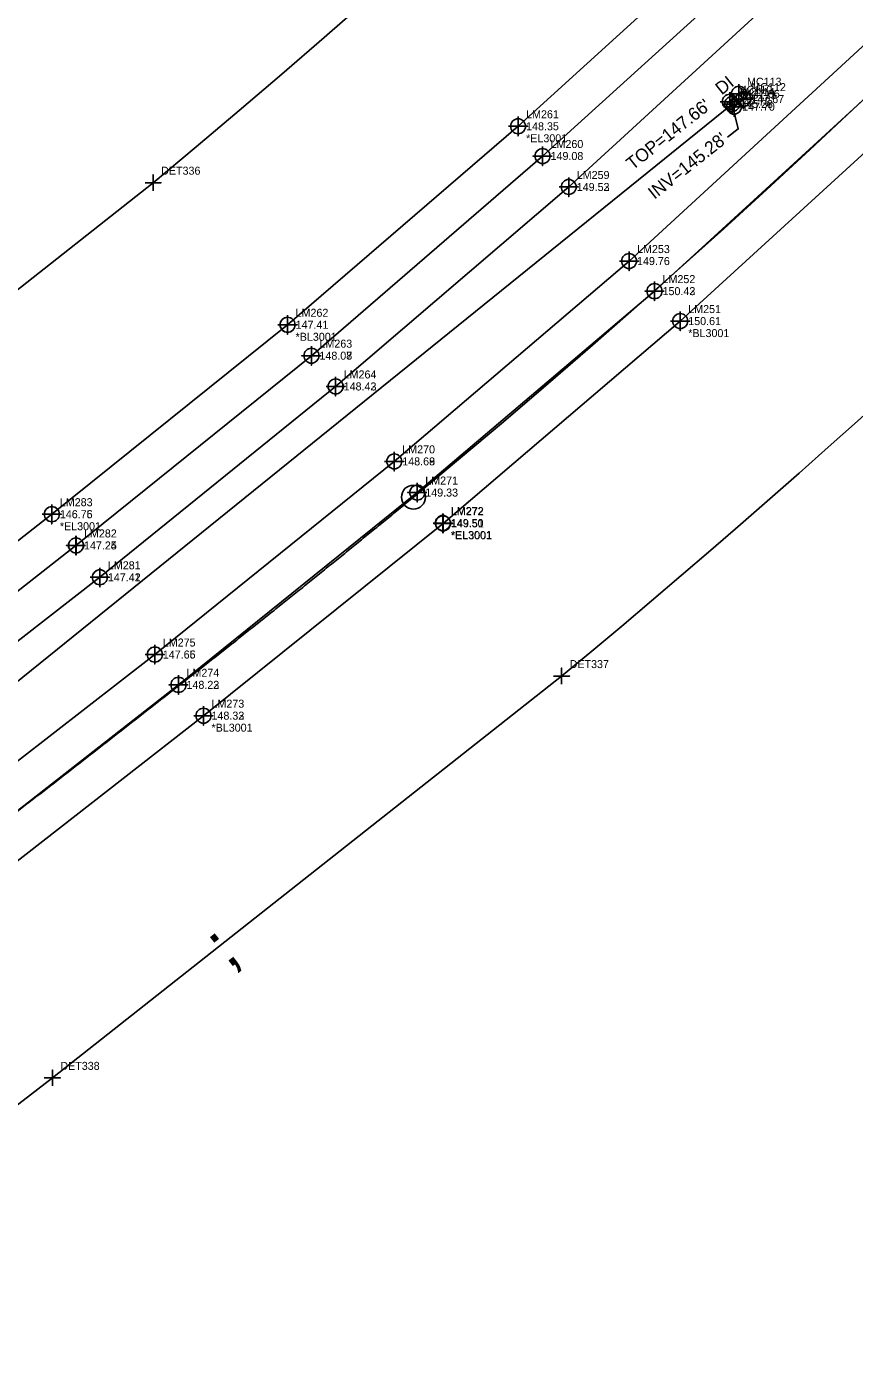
# Model space of a CAD drawing. Extents: x 2262665 to 2270527, y 505476 to 514960.
# Drawn here: x 2265152.7 to 2265411.2, y 507873.1 to 508285.7 of the extents above; entities that cross this region are included whole.
import ezdxf

# ---------------------------------------------------------------- set-up
doc = ezdxf.new("R2010")
doc.units = 0
for name, color, linetype in [('Exist Horizontal Alignment', 7, 'Continuous'), ('Exist Property Corner CELL', 7, 'Continuous'), ('Exist Property Corner Cogo Number', 7, 'Continuous'), ('Exist Right of Way Control of Access CA Symbol CELL', 7, 'Continuous'), ('Exist Right of Way Control of Access Line', 7, 'Continuous'), ('Exist Roads EOP', 7, 'Continuous'), ('Exist Roads EOP Cogo Comment', 7, 'Continuous'), ('Exist Roads EOP Cogo Elevation', 7, 'Continuous'), ('Exist Roads EOP Cogo Number', 7, 'Continuous'), ('Exist Roads EOP Cogo Point CELL', 7, 'Continuous'), ('Exist Roads EOT', 7, 'Continuous'), ('Exist Roads EOT Cogo Elevation', 7, 'Continuous'), ('Exist Roads EOT Cogo Number', 7, 'Continuous'), ('Exist Roads EOT Cogo Point CELL', 7, 'Continuous'), ('Exist Structure Minor Drop Inlet', 7, 'Continuous'), ('Exist Structure Minor Drop Inlet Cogo Elevation', 7, 'Continuous'), ('Exist Structure Minor Drop Inlet Cogo Number', 7, 'Continuous'), ('Exist Structure Minor Drop Inlet Cogo Point CELL', 7, 'Continuous'), ('Exist Structure Minor Drop Inlet Text', 7, 'Continuous'), ('Exist Structure Minor Drop Inlet Top Elevation', 7, 'Continuous'), ('Exist Structure Minor Pipes RCP 15 Inch', 7, 'Continuous'), ('Exist Structure Minor Pipes RCP 15 Inch Cogo Elevation', 7, 'Continuous'), ('Exist Structure Minor Pipes RCP 15 Inch Cogo Number', 7, 'Continuous'), ('Exist Structure Minor Pipes RCP 15 Inch Cogo Point CELL', 7, 'Continuous'), ('Exist Structure Minor Pipes RCP 15 Inch Invert', 7, 'Continuous'), ('Exist Structure Minor Pipes RCP 15 Inch Leader', 7, 'Continuous')]:
    doc.layers.add(name, color=color, linetype=linetype)

msp = doc.modelspace()

# ---------------------------------------------------------------- linework, layer by layer
at = {"layer": 'Exist Horizontal Alignment'}
msp.add_circle((2265273.5, 508138.73), 3.75, dxfattribs=at)
msp.add_arc((2263436.25, 510359.19), 2882, 309.60499, 355.6461, dxfattribs=at)
msp.add_spline([(2265116.51, 508014.84), (2265118.65, 508016.49), (2265120.79, 508018.14), (2265122.93, 508019.79), (2265125.07, 508021.44), (2265127.21, 508023.09), (2265129.35, 508024.74), (2265131.49, 508026.39), (2265133.63, 508028.04), (2265135.77, 508029.69), (2265137.91, 508031.34), (2265140.05, 508032.99), (2265142.19, 508034.64), (2265144.33, 508036.29), (2265146.47, 508037.94), (2265148.61, 508039.6), (2265150.74, 508041.25), (2265152.88, 508042.9), (2265155.02, 508044.56), (2265157.16, 508046.21), (2265159.29, 508047.87), (2265161.43, 508049.52), (2265163.57, 508051.18), (2265165.7, 508052.83), (2265167.84, 508054.49), (2265169.97, 508056.15), (2265172.11, 508057.81), (2265174.24, 508059.47), (2265176.37, 508061.13), (2265178.5, 508062.79), (2265180.64, 508064.45), (2265182.77, 508066.11), (2265184.9, 508067.77), (2265187.03, 508069.44), (2265189.16, 508071.1), (2265191.28, 508072.77), (2265193.41, 508074.44), (2265195.54, 508076.1), (2265197.67, 508077.77), (2265199.79, 508079.44), (2265201.92, 508081.11), (2265204.04, 508082.78), (2265206.16, 508084.46), (2265208.28, 508086.13), (2265210.4, 508087.81), (2265212.52, 508089.48), (2265214.64, 508091.16), (2265216.76, 508092.84), (2265218.88, 508094.52), (2265220.99, 508096.2), (2265223.11, 508097.88), (2265225.22, 508099.57), (2265227.34, 508101.25), (2265229.45, 508102.94), (2265231.56, 508104.63), (2265233.67, 508106.32), (2265235.78, 508108.01), (2265237.88, 508109.7), (2265239.99, 508111.4), (2265242.09, 508113.09), (2265244.2, 508114.79), (2265246.3, 508116.49), (2265248.4, 508118.19), (2265250.5, 508119.89), (2265252.6, 508121.59), (2265254.69, 508123.3), (2265256.79, 508125.01), (2265258.88, 508126.72), (2265260.97, 508128.43), (2265263.07, 508130.14), (2265265.15, 508131.85), (2265267.24, 508133.57), (2265269.33, 508135.29), (2265271.41, 508137.01), (2265273.5, 508138.73)], degree=3, dxfattribs=at)
at = {"layer": 'Exist Property Corner CELL'}
for p, q in [((2265192.25, 508236.92), (2265192.25, 508236.92)), ((2265319.75, 508082.83), (2265319.75, 508082.83)), ((2265160.79, 507957.36), (2265160.79, 507957.36))]:
    msp.add_line(p, q, dxfattribs=at)
for points in [[(2265189.75, 508236.92), (2265194.75, 508236.92), (2265192.25, 508236.92), (2265192.25, 508239.42), (2265192.25, 508234.42)], [(2265317.25, 508082.83), (2265322.25, 508082.83), (2265319.75, 508082.83), (2265319.75, 508085.33), (2265319.75, 508080.33)], [(2265158.29, 507957.36), (2265163.29, 507957.36), (2265160.79, 507957.36), (2265160.79, 507959.86), (2265160.79, 507954.86)]]:
    msp.add_lwpolyline(points, dxfattribs=at)
at = {"layer": 'Exist Right of Way Control of Access CA Symbol CELL'}
msp.add_line((2265216.9, 508001.65), (2265216.9, 508001.65), dxfattribs=at)
at = {"layer": 'Exist Right of Way Control of Access Line'}
for p, q in [((2265038.72, 508115.78), (2265192.25, 508236.92)), ((2265160.79, 507957.36), (2265319.75, 508082.83)), ((2264610.44, 507533.27), (2265160.79, 507957.36))]:
    msp.add_line(p, q, dxfattribs=at)
for radius, end in [(2754.56, 355.6461), (2954.56, 339.73535)]:
    msp.add_arc((2263436.25, 510359.19), radius, 309.60499, end, dxfattribs=at)
at = {"layer": 'Exist Roads EOP'}
for points in [[(2264604.13, 507673.17), (2264652.18, 507710.12), (2264729.46, 507770.12), (2264804.34, 507827.5), (2264878.61, 507884.49), (2264953.4, 507941.83), (2265025.73, 507997.77), (2265100.61, 508055.34), (2265175.62, 508113.68), (2265249.21, 508173.29), (2265321.97, 508235.58), (2265396.59, 508304.14), (2265463.32, 508369.68), (2265525.52, 508435.63), (2265587.08, 508505.56), (2265646.09, 508576.73), (2265702.44, 508648.91), (2265758.48, 508726.47), (2265812.43, 508805.68)], [(2264622.96, 507650.09), (2264669.69, 507686.11), (2264747.6, 507746.03), (2264823.02, 507803.99), (2264895.49, 507859.73), (2264970.56, 507917.69), (2265042.91, 507973.75), (2265117.63, 508031.26), (2265192.77, 508089.56), (2265267.51, 508149.88), (2265340.79, 508212.44), (2265416.18, 508281.7), (2265483.07, 508347.24), (2265547.56, 508415.53), (2265609.81, 508485.51), (2265669.26, 508556.91), (2265726.09, 508630), (2265782.72, 508708.15), (2265836.53, 508788.04)], [(2264589.08, 507692.53), (2264637.26, 507729.66), (2264714.99, 507789.55), (2264789.92, 507847.03), (2264863.62, 507903.58), (2264937.94, 507960.85), (2265012.05, 508017.75), (2265086.27, 508074.98), (2265160.63, 508133.38), (2265234.21, 508192.54), (2265306.16, 508254.54), (2265379.88, 508321.65), (2265446.65, 508386.97), (2265507.93, 508452.08), (2265569.21, 508521.55), (2265627.59, 508592.93), (2265683.12, 508664.16), (2265738.79, 508741.02), (2265756.07, 508766.2)], [(2265684.68, 508536.79), (2265628.24, 508469.05), (2265566.02, 508398.87), (2265500.44, 508329.56), (2265432.73, 508263.15), (2265356.77, 508193.7), (2265282.75, 508130.52), (2265207.97, 508070.47), (2265132.61, 508011.69), (2265056.74, 507953.11), (2264985.01, 507897.76), (2264909.79, 507839.57), (2264837.99, 507784.49), (2264762.26, 507726.1), (2264683.86, 507665.88)]]:
    msp.add_lwpolyline(points, dxfattribs=at)
at = {"layer": 'Exist Roads EOP Cogo Point CELL'}
for points in [[(2265306.16, 508257.54), (2265306.16, 508251.54), (2265306.16, 508254.54), (2265309.16, 508254.54), (2265303.16, 508254.54)], [(2265306.16, 508257.54), (2265306.16, 508251.54), (2265306.16, 508254.54), (2265309.16, 508254.54), (2265303.16, 508254.54)], [(2265321.97, 508238.58), (2265321.97, 508232.58), (2265321.97, 508235.58), (2265324.97, 508235.58), (2265318.97, 508235.58)], [(2265321.97, 508238.58), (2265321.97, 508232.58), (2265321.97, 508235.58), (2265324.97, 508235.58), (2265318.97, 508235.58)], [(2265340.79, 508215.44), (2265340.79, 508209.44), (2265340.79, 508212.44), (2265343.79, 508212.44), (2265337.79, 508212.44)], [(2265340.79, 508215.45), (2265340.79, 508209.45), (2265340.79, 508212.45), (2265343.79, 508212.45), (2265337.79, 508212.45)], [(2265234.21, 508195.54), (2265234.21, 508189.54), (2265234.21, 508192.54), (2265237.21, 508192.54), (2265231.21, 508192.54)], [(2265234.22, 508195.55), (2265234.22, 508189.55), (2265234.22, 508192.55), (2265237.22, 508192.55), (2265231.22, 508192.55)], [(2265356.77, 508196.7), (2265356.77, 508190.7), (2265356.77, 508193.7), (2265359.77, 508193.7), (2265353.77, 508193.7)], [(2265356.77, 508196.7), (2265356.77, 508190.7), (2265356.77, 508193.7), (2265359.77, 508193.7), (2265353.77, 508193.7)], [(2265249.22, 508176.29), (2265249.22, 508170.29), (2265249.22, 508173.29), (2265252.22, 508173.29), (2265246.22, 508173.29)], [(2265249.21, 508176.29), (2265249.21, 508170.29), (2265249.21, 508173.29), (2265252.21, 508173.29), (2265246.21, 508173.29)], [(2265267.51, 508152.89), (2265267.51, 508146.89), (2265267.51, 508149.89), (2265270.51, 508149.89), (2265264.51, 508149.89)], [(2265267.51, 508152.88), (2265267.51, 508146.88), (2265267.51, 508149.88), (2265270.51, 508149.88), (2265264.51, 508149.88)], [(2265160.63, 508136.38), (2265160.63, 508130.38), (2265160.63, 508133.38), (2265163.63, 508133.38), (2265157.63, 508133.38)], [(2265160.64, 508136.39), (2265160.64, 508130.39), (2265160.64, 508133.39), (2265163.64, 508133.39), (2265157.64, 508133.39)], [(2265282.65, 508133.64), (2265282.65, 508127.64), (2265282.65, 508130.64), (2265285.65, 508130.64), (2265279.65, 508130.64)], [(2265282.75, 508133.52), (2265282.75, 508127.52), (2265282.75, 508130.52), (2265285.75, 508130.52), (2265279.75, 508130.52)], [(2265175.62, 508116.68), (2265175.62, 508110.68), (2265175.62, 508113.68), (2265178.62, 508113.68), (2265172.62, 508113.68)], [(2265175.63, 508116.68), (2265175.63, 508110.68), (2265175.63, 508113.68), (2265178.63, 508113.68), (2265172.63, 508113.68)], [(2265192.77, 508092.56), (2265192.77, 508086.56), (2265192.77, 508089.56), (2265195.77, 508089.56), (2265189.77, 508089.56)], [(2265192.78, 508092.57), (2265192.78, 508086.57), (2265192.78, 508089.57), (2265195.78, 508089.57), (2265189.78, 508089.57)], [(2265207.96, 508073.47), (2265207.96, 508067.47), (2265207.96, 508070.47), (2265210.96, 508070.47), (2265204.96, 508070.47)], [(2265207.97, 508073.47), (2265207.97, 508067.47), (2265207.97, 508070.47), (2265210.97, 508070.47), (2265204.97, 508070.47)]]:
    msp.add_lwpolyline(points, dxfattribs=at)
for centre in [(2265306.16, 508254.54), (2265306.16, 508254.54), (2265321.97, 508235.58), (2265321.97, 508235.58), (2265340.79, 508212.45), (2265340.79, 508212.44), (2265234.22, 508192.55), (2265234.21, 508192.54), (2265356.77, 508193.7), (2265356.77, 508193.7), (2265249.22, 508173.29), (2265249.21, 508173.29), (2265267.51, 508149.88), (2265267.51, 508149.89), (2265160.64, 508133.39), (2265160.63, 508133.38), (2265282.65, 508130.64), (2265282.75, 508130.52), (2265175.63, 508113.68), (2265175.62, 508113.68), (2265192.78, 508089.57), (2265192.77, 508089.56), (2265207.97, 508070.47), (2265207.96, 508070.47)]:
    msp.add_circle(centre, 2.34, dxfattribs=at)
at = {"layer": 'Exist Roads EOT'}
for points in [[(2264355.6, 507490.59), (2264438.39, 507557.92), (2264515.74, 507619.63), (2264596.53, 507682.98), (2264644.8, 507719.95), (2264722.22, 507780.13), (2264797.31, 507837.32), (2264871.27, 507893.95), (2264945.98, 507951.46), (2265019.16, 508007.99), (2265093.77, 508065.17), (2265168.17, 508123.63), (2265241.66, 508182.89), (2265313.79, 508245.24), (2265388.67, 508313.15), (2265454.9, 508378.68), (2265516.64, 508444.01), (2265578.28, 508513.6), (2265637.19, 508584.7), (2265692.99, 508656.91), (2265748.78, 508733.7), (2265775.13, 508772.3)], [(2264387.25, 507447.54), (2264469.24, 507514.31), (2264548.37, 507577.38), (2264630.86, 507640.65), (2264676.76, 507676.3), (2264754.66, 507736.06), (2264830.22, 507794.41), (2264902.47, 507849.79), (2264977.44, 507907.47), (2265049.71, 507963.66), (2265125.01, 508021.39), (2265200.16, 508080.1), (2265274.69, 508140.15), (2265348.74, 508203.05), (2265424.49, 508272.43), (2265491.61, 508338.47), (2265557.1, 508407.36), (2265618.9, 508477.1), (2265678.7, 508548.94), (2265735.91, 508622.32), (2265792.76, 508700.56), (2265828.5, 508753.55)]]:
    msp.add_lwpolyline(points, dxfattribs=at)
at = {"layer": 'Exist Roads EOT Cogo Point CELL'}
for points in [[(2265313.79, 508248.24), (2265313.79, 508242.24), (2265313.79, 508245.24), (2265310.79, 508245.24), (2265316.79, 508245.24)], [(2265313.8, 508248.25), (2265313.8, 508242.25), (2265313.8, 508245.25), (2265310.8, 508245.25), (2265316.8, 508245.25)], [(2265348.75, 508206.05), (2265348.75, 508200.05), (2265348.75, 508203.05), (2265345.75, 508203.05), (2265351.75, 508203.05)], [(2265348.74, 508206.05), (2265348.74, 508200.05), (2265348.74, 508203.05), (2265345.74, 508203.05), (2265351.74, 508203.05)], [(2265241.66, 508185.89), (2265241.66, 508179.89), (2265241.66, 508182.89), (2265238.66, 508182.89), (2265244.66, 508182.89)], [(2265241.66, 508185.89), (2265241.66, 508179.89), (2265241.66, 508182.89), (2265238.66, 508182.89), (2265244.66, 508182.89)], [(2265274.69, 508143.15), (2265274.69, 508137.15), (2265274.69, 508140.15), (2265271.69, 508140.15), (2265277.69, 508140.15)], [(2265274.7, 508143.15), (2265274.7, 508137.15), (2265274.7, 508140.15), (2265271.7, 508140.15), (2265277.7, 508140.15)], [(2265168.17, 508126.63), (2265168.17, 508120.63), (2265168.17, 508123.63), (2265165.17, 508123.63), (2265171.17, 508123.63)], [(2265168.18, 508126.63), (2265168.18, 508120.63), (2265168.18, 508123.63), (2265165.18, 508123.63), (2265171.18, 508123.63)], [(2265200.16, 508083.1), (2265200.16, 508077.1), (2265200.16, 508080.1), (2265197.16, 508080.1), (2265203.16, 508080.1)], [(2265200.16, 508083.1), (2265200.16, 508077.1), (2265200.16, 508080.1), (2265197.16, 508080.1), (2265203.16, 508080.1)]]:
    msp.add_lwpolyline(points, dxfattribs=at)
for centre in [(2265313.8, 508245.25), (2265313.79, 508245.24), (2265348.75, 508203.05), (2265348.74, 508203.05), (2265241.66, 508182.89), (2265241.66, 508182.89), (2265274.7, 508140.15), (2265274.69, 508140.15), (2265168.18, 508123.63), (2265168.17, 508123.63), (2265200.16, 508080.1), (2265200.16, 508080.1)]:
    msp.add_circle(centre, 2.34, dxfattribs=at)
at = {"layer": 'Exist Structure Minor Drop Inlet'}
msp.add_lwpolyline([(2265373.57, 508260.66), (2265376.47, 508263.03), (2265375.11, 508264.69), (2265372.21, 508262.32)], close=True, dxfattribs=at)
at = {"layer": 'Exist Structure Minor Drop Inlet Cogo Point CELL'}
for points in [[(2265372.23, 508265.19), (2265372.23, 508259.19), (2265372.23, 508262.19), (2265375.23, 508262.19), (2265369.23, 508262.19)], [(2265375.11, 508267.69), (2265375.11, 508261.69), (2265375.11, 508264.69), (2265378.11, 508264.69), (2265372.11, 508264.69)], [(2265376.47, 508266.03), (2265376.47, 508260.03), (2265376.47, 508263.03), (2265379.47, 508263.03), (2265373.47, 508263.03)], [(2265373.57, 508263.66), (2265373.57, 508257.66), (2265373.57, 508260.66), (2265376.57, 508260.66), (2265370.57, 508260.66)]]:
    msp.add_lwpolyline(points, dxfattribs=at)
for centre in [(2265372.23, 508262.19), (2265375.11, 508264.69), (2265376.47, 508263.03), (2265373.57, 508260.66)]:
    msp.add_circle(centre, 2.34, dxfattribs=at)
at = {"layer": 'Exist Structure Minor Pipes RCP 15 Inch'}
msp.add_line((2265372.98, 508261.49), (2264951.02, 507920.49), dxfattribs=at)
at = {"layer": 'Exist Structure Minor Pipes RCP 15 Inch Cogo Point CELL'}
msp.add_lwpolyline([(2265372.98, 508264.49), (2265372.98, 508258.49), (2265372.98, 508261.49), (2265375.98, 508261.49), (2265369.98, 508261.49)], dxfattribs=at)
msp.add_circle((2265372.98, 508261.49), 2.34, dxfattribs=at)
at = {"layer": 'Exist Structure Minor Pipes RCP 15 Inch Leader'}
msp.add_lwpolyline([(2265372.98, 508261.49), (2265374.9, 508253.69), (2265371.48, 508251.1)], dxfattribs=at)

# ---------------------------------------------------------------- texts
at = {"layer": 'Exist Property Corner Cogo Number'}
for s, p in [('DET336', (2265194.75, 508239.42)), ('DET337', (2265322.25, 508085.33)), ('DET338', (2265163.29, 507959.86))]:
    msp.add_text(s, height=2.5, dxfattribs=at).set_placement(p)
at = {"layer": 'Exist Right of Way Control of Access CA Symbol CELL'}
msp.add_text(';', height=15, rotation=38.2837, dxfattribs=at).set_placement((2265215.66, 507991.11))
at = {"layer": 'Exist Roads EOP Cogo Comment'}
for s, p in [('*EL3001', (2265308.66, 508249.54)), ('*EL3001', (2265308.66, 508249.54)), ('*BL3001', (2265236.72, 508187.55)), ('*BL3001', (2265236.71, 508187.54)), ('*BL3001', (2265359.27, 508188.7)), ('*BL3001', (2265359.27, 508188.7)), ('*EL3001', (2265163.13, 508128.38)), ('*EL3001', (2265163.14, 508128.39)), ('*EL3001', (2265285.15, 508125.64)), ('*EL3001', (2265285.25, 508125.52)), ('*BL3001', (2265210.47, 508065.47)), ('*BL3001', (2265210.46, 508065.47))]:
    msp.add_text(s, height=2.5, dxfattribs=at).set_placement(p)
at = {"layer": 'Exist Roads EOP Cogo Elevation'}
for s, p in [('148.35', (2265308.66, 508253.29)), ('148.35', (2265308.66, 508253.29)), ('149.52', (2265324.47, 508234.33)), ('149.53', (2265324.47, 508234.33)), ('149.76', (2265343.29, 508211.2)), ('149.76', (2265343.29, 508211.19)), ('150.61', (2265359.27, 508192.45)), ('150.61', (2265359.27, 508192.45)), ('147.41', (2265236.72, 508191.3)), ('147.41', (2265236.71, 508191.29)), ('148.43', (2265251.72, 508172.04)), ('148.42', (2265251.71, 508172.04)), ('148.68', (2265270.01, 508148.63)), ('148.69', (2265270.01, 508148.64)), ('146.76', (2265163.14, 508132.14)), ('146.75', (2265163.13, 508132.13)), ('149.50', (2265285.15, 508129.39)), ('149.51', (2265285.25, 508129.27)), ('147.42', (2265178.13, 508112.43)), ('147.41', (2265178.12, 508112.43)), ('147.66', (2265195.28, 508088.32)), ('147.65', (2265195.27, 508088.31)), ('148.33', (2265210.47, 508069.22)), ('148.32', (2265210.46, 508069.22))]:
    msp.add_text(s, height=2.5, dxfattribs=at).set_placement(p)
at = {"layer": 'Exist Roads EOP Cogo Number'}
for s, p in [('LM261', (2265308.66, 508257.04)), ('LM261', (2265308.66, 508257.04)), ('LM259', (2265324.47, 508238.08)), ('LM259', (2265324.47, 508238.08)), ('LM253', (2265343.29, 508214.95)), ('LM253', (2265343.29, 508214.94)), ('LM251', (2265359.27, 508196.2)), ('LM251', (2265359.27, 508196.2)), ('LM262', (2265236.72, 508195.05)), ('LM262', (2265236.71, 508195.04)), ('LM264', (2265251.72, 508175.79)), ('LM264', (2265251.71, 508175.79)), ('LM270', (2265270.01, 508152.38)), ('LM270', (2265270.01, 508152.39)), ('LM283', (2265163.14, 508135.89)), ('LM283', (2265163.13, 508135.88)), ('LM272', (2265285.15, 508133.14)), ('LM272', (2265285.25, 508133.02)), ('LM281', (2265178.13, 508116.18)), ('LM281', (2265178.12, 508116.18)), ('LM275', (2265195.28, 508092.07)), ('LM275', (2265195.27, 508092.06)), ('LM273', (2265210.47, 508072.97)), ('LM273', (2265210.46, 508072.97))]:
    msp.add_text(s, height=2.5, dxfattribs=at).set_placement(p)
at = {"layer": 'Exist Roads EOT Cogo Elevation'}
for s, p in [('149.08', (2265316.3, 508244)), ('149.08', (2265316.29, 508243.99)), ('150.43', (2265351.25, 508201.8)), ('150.42', (2265351.24, 508201.8)), ('148.08', (2265244.16, 508181.64)), ('148.07', (2265244.16, 508181.64)), ('149.33', (2265277.2, 508138.9)), ('149.33', (2265277.19, 508138.9)), ('147.25', (2265170.68, 508122.38)), ('147.24', (2265170.67, 508122.38)), ('148.22', (2265202.66, 508078.85)), ('148.23', (2265202.66, 508078.85))]:
    msp.add_text(s, height=2.5, dxfattribs=at).set_placement(p)
at = {"layer": 'Exist Roads EOT Cogo Number'}
for s, p in [('LM260', (2265316.3, 508247.75)), ('LM260', (2265316.29, 508247.74)), ('LM252', (2265351.25, 508205.55)), ('LM252', (2265351.24, 508205.55)), ('LM263', (2265244.16, 508185.39)), ('LM263', (2265244.16, 508185.39)), ('LM271', (2265277.2, 508142.65)), ('LM271', (2265277.19, 508142.65)), ('LM282', (2265170.68, 508126.13)), ('LM282', (2265170.67, 508126.13)), ('LM274', (2265202.66, 508082.6)), ('LM274', (2265202.66, 508082.6))]:
    msp.add_text(s, height=2.5, dxfattribs=at).set_placement(p)
at = {"layer": 'Exist Structure Minor Drop Inlet Cogo Elevation'}
for s, p in [('147.66', (2265377.61, 508263.44)), ('147.67', (2265378.97, 508261.78)), ('147.73', (2265374.73, 508260.94)), ('147.70', (2265376.07, 508259.41))]:
    msp.add_text(s, height=2.5, dxfattribs=at).set_placement(p)
at = {"layer": 'Exist Structure Minor Drop Inlet Cogo Number'}
for s, p in [('MC113', (2265377.61, 508267.19)), ('MC110', (2265374.73, 508264.69)), ('MC111', (2265376.07, 508263.16)), ('MC112', (2265378.97, 508265.53))]:
    msp.add_text(s, height=2.5, dxfattribs=at).set_placement(p)
at = {"layer": 'Exist Structure Minor Drop Inlet Text'}
msp.add_text('DI', height=4, rotation=38.4598, dxfattribs=at).set_placement((2265369.72, 508264.15))
at = {"layer": 'Exist Structure Minor Drop Inlet Top Elevation'}
msp.add_text("TOP=147.66'", height=4, rotation=38.3453, dxfattribs=at).set_placement((2265341.92, 508240.7))
at = {"layer": 'Exist Structure Minor Pipes RCP 15 Inch Cogo Elevation'}
msp.add_text('145.28', height=2.5, dxfattribs=at).set_placement((2265375.48, 508260.24))
at = {"layer": 'Exist Structure Minor Pipes RCP 15 Inch Cogo Number'}
msp.add_text('MC114', height=2.5, dxfattribs=at).set_placement((2265375.48, 508263.99))
at = {"layer": 'Exist Structure Minor Pipes RCP 15 Inch Invert'}
msp.add_text("INV=145.28'", height=4, rotation=38.3453, dxfattribs=at).set_placement((2265348.71, 508231.56))

doc.saveas('drawing.dxf')
